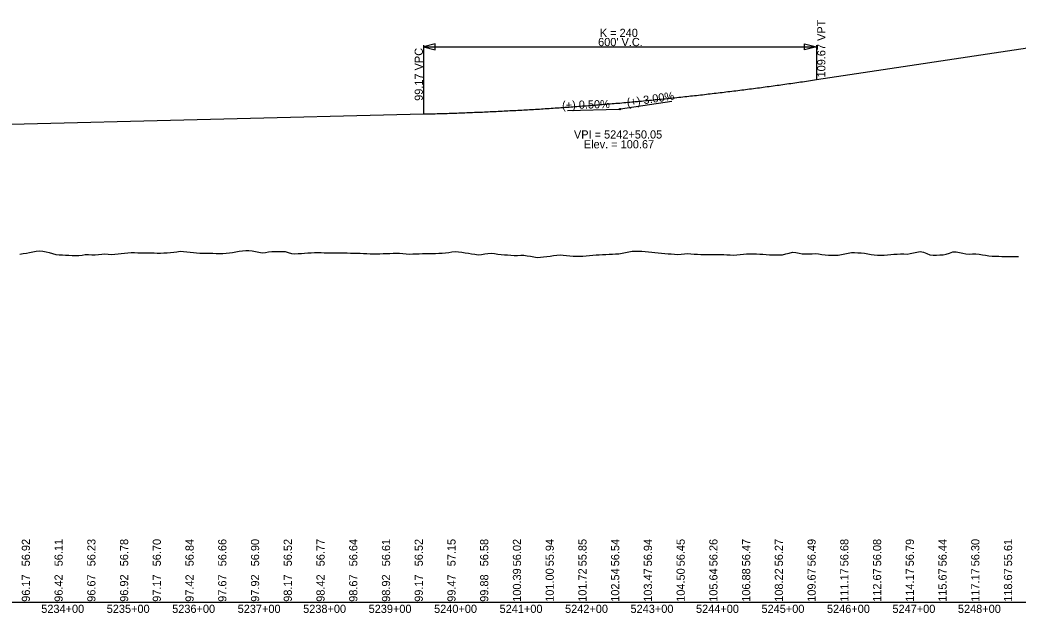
# Model space of a CAD drawing. Extents: x 2147288 to 2220488, y 740833 to 759333.
# Drawn here: x 2155715 to 2157239, y 758067 to 758973 of the extents above; entities that cross this region are included whole.
import ezdxf

# ---------------------------------------------------------------- set-up
doc = ezdxf.new("R2010")
doc.units = 0
for name, color, linetype in [('RD_DDB_GradeTX', 7, 'Continuous'), ('RD_DDB_Profile_EX', 7, 'Continuous'), ('RD_DDB_Profile_Lbl', 7, 'Continuous'), ('RD_DDB_Profile_PR', 7, 'Continuous'), ('RD_DDB_StaTX', 7, 'Continuous'), ('RD_DDB_StripGrade', 7, 'Continuous'), ('RD_DDB_VCLbl', 7, 'Continuous'), ('RD_GPK_Profile_Cell', 7, 'Continuous')]:
    doc.layers.add(name, color=color, linetype=linetype)

msp = doc.modelspace()

# ---------------------------------------------------------------- linework, layer by layer
at = {"layer": 'RD_DDB_GradeTX'}
for p, q in [((2156710.2, 758848.6), (2156632.1, 758836.9)), ((2156551.2, 758834.8), (2156630.1, 758836.7))]:
    msp.add_line(p, q, dxfattribs=at)
msp.add_circle((2156631.1, 758836.8), 1, dxfattribs=at)
at = {"layer": 'RD_DDB_Profile_EX'}
for points in [[(2155714.6, 758615.3), (2155719.6, 758616), (2155724.6, 758616.8), (2155729.6, 758617.7), (2155734.6, 758618.6), (2155739.6, 758619.6), (2155744.6, 758620.1), (2155749.6, 758620), (2155754.6, 758618.9), (2155759.6, 758617.5), (2155764.6, 758616), (2155769.6, 758614.5), (2155774.6, 758614), (2155779.6, 758614.1), (2155784.6, 758613.9), (2155789.6, 758613.6), (2155794.6, 758613.4), (2155799.6, 758613.2), (2155804.6, 758613.4), (2155809.6, 758613.8), (2155814.6, 758614.7), (2155819.6, 758614.7), (2155824.6, 758614), (2155829.6, 758614.4), (2155834.6, 758614.9), (2155839.6, 758615.3), (2155844.6, 758615.7), (2155849.6, 758615.4), (2155854.6, 758614.8), (2155859.6, 758615.3), (2155864.6, 758615.9), (2155869.6, 758616.3), (2155874.6, 758616.8), (2155879.6, 758617.2), (2155884.6, 758617.7), (2155889.6, 758617.5), (2155894.6, 758617.2), (2155899.6, 758617.1), (2155904.6, 758617.2), (2155909.6, 758617.2), (2155914.6, 758617.3), (2155919.6, 758617.2), (2155924.6, 758616.9), (2155929.6, 758616.8), (2155934.6, 758617.1), (2155939.6, 758617.3), (2155944.6, 758617.5), (2155949.6, 758618), (2155954.6, 758618.9), (2155959.6, 758619.7), (2155964.6, 758619.3), (2155969.6, 758618.8), (2155974.6, 758618.3), (2155979.6, 758617.8), (2155984.6, 758617.2), (2155989.6, 758616.7), (2155994.6, 758616.6), (2155999.6, 758616.7), (2156004.6, 758616.7), (2156009.6, 758616.6), (2156014.6, 758616.4), (2156019.6, 758616.3), (2156024.6, 758616.3), (2156029.6, 758616.6), (2156034.6, 758617)], [(2156034.6, 758617), (2156039.6, 758617.9), (2156044.6, 758618.8), (2156049.6, 758619.7), (2156054.6, 758620.5), (2156059.6, 758620.7), (2156064.6, 758620.9), (2156069.6, 758620.4), (2156074.6, 758619.3), (2156079.6, 758618.3), (2156084.6, 758617.2), (2156089.6, 758617.6), (2156094.6, 758618.5), (2156099.6, 758619.3), (2156104.6, 758619.4), (2156109.6, 758619.4), (2156114.6, 758619.5), (2156119.6, 758619.1), (2156124.6, 758617.6), (2156129.6, 758616.1), (2156134.6, 758615.7), (2156139.6, 758616), (2156144.6, 758616.4), (2156149.6, 758616.7), (2156154.6, 758617), (2156159.6, 758617.3), (2156164.6, 758617.6), (2156169.6, 758617.7), (2156174.6, 758617.5), (2156179.6, 758617.3), (2156184.6, 758617.1), (2156189.6, 758617.1), (2156194.6, 758617.2), (2156199.6, 758617.2), (2156204.6, 758617.2), (2156209.6, 758617.1), (2156214.6, 758617), (2156219.6, 758616.9), (2156224.6, 758616.8), (2156229.6, 758616.7), (2156234.6, 758616.5), (2156239.6, 758616.4), (2156244.6, 758616.1), (2156249.6, 758615.9), (2156254.6, 758615.7), (2156259.6, 758615.7), (2156264.6, 758615.9), (2156269.6, 758616.1), (2156274.6, 758616.3), (2156279.6, 758616.4), (2156284.6, 758616.6), (2156289.6, 758616.7), (2156294.6, 758616.6), (2156299.6, 758616.1), (2156304.6, 758615.7), (2156309.6, 758615.4), (2156314.6, 758615.5), (2156319.6, 758615.7), (2156324.6, 758615.9), (2156329.6, 758616), (2156334.6, 758616.1), (2156339.6, 758616.2), (2156344.6, 758616.3), (2156349.6, 758616.4), (2156354.6, 758616.5), (2156359.6, 758616.6), (2156364.6, 758617), (2156369.6, 758617.8), (2156374.6, 758618.6), (2156379.6, 758619.4), (2156384.6, 758618.7), (2156389.6, 758618), (2156394.6, 758617.2), (2156399.6, 758616.5), (2156404.6, 758615.7), (2156409.6, 758615), (2156414.6, 758614.2), (2156419.6, 758614.8), (2156424.6, 758615.5), (2156429.6, 758616.2), (2156434.6, 758616.6), (2156439.6, 758616), (2156444.6, 758615.4), (2156449.6, 758614.8), (2156454.6, 758614.4), (2156459.6, 758614), (2156464.6, 758613.7), (2156469.6, 758613.3), (2156474.6, 758613.4), (2156479.6, 758613.5), (2156484.6, 758613.6), (2156489.6, 758612.8), (2156494.6, 758612), (2156499.6, 758611.1), (2156504.6, 758610.3), (2156509.6, 758610.8), (2156514.6, 758611.2), (2156519.6, 758611.7), (2156524.6, 758612.3), (2156529.6, 758612.9), (2156534.6, 758613.5)], [(2156534.6, 758613.5), (2156539.6, 758614.2), (2156544.6, 758613.6), (2156549.6, 758613), (2156554.6, 758612.4), (2156559.6, 758612.2), (2156564.6, 758612.2), (2156569.6, 758612.1), (2156574.6, 758612.1), (2156579.6, 758612.5), (2156584.6, 758613.1), (2156589.6, 758613.6), (2156594.6, 758614.1), (2156599.6, 758614.3), (2156604.6, 758614.6), (2156609.6, 758614.9), (2156614.6, 758615.1), (2156619.6, 758615.3), (2156624.6, 758615.5), (2156629.6, 758615.8), (2156634.6, 758616.8), (2156639.6, 758617.9), (2156644.6, 758618.9), (2156649.6, 758619.7), (2156654.6, 758619.7), (2156659.6, 758619.6), (2156664.6, 758619.6), (2156669.6, 758619.1), (2156674.6, 758618.7), (2156679.6, 758618.3), (2156684.6, 758617.8), (2156689.6, 758617.3), (2156694.6, 758616.9), (2156699.6, 758616.4), (2156704.6, 758615.9), (2156709.6, 758615.5), (2156714.6, 758615.1), (2156719.6, 758614.7), (2156724.6, 758615.1), (2156729.6, 758615.5), (2156734.6, 758616), (2156739.6, 758615.7), (2156744.6, 758615.3), (2156749.6, 758615), (2156754.6, 758614.7), (2156759.6, 758614.7), (2156764.6, 758614.7), (2156769.6, 758614.7), (2156774.6, 758614.7), (2156779.6, 758614.7), (2156784.6, 758614.7), (2156789.6, 758614.8), (2156794.6, 758614.4), (2156799.6, 758614.1), (2156804.6, 758613.8), (2156809.6, 758614.2), (2156814.6, 758614.7), (2156819.6, 758615.2), (2156824.6, 758615.7), (2156829.6, 758615.8), (2156834.6, 758615.8), (2156839.6, 758615.7), (2156844.6, 758615.4), (2156849.6, 758615.1), (2156854.6, 758614.7), (2156859.6, 758614.3), (2156864.6, 758614.3), (2156869.6, 758614.4), (2156874.6, 758614.4), (2156879.6, 758614.4), (2156884.6, 758615.5), (2156889.6, 758616.9), (2156894.6, 758618.3), (2156899.6, 758617.7), (2156904.6, 758616.6), (2156909.6, 758615.5), (2156914.6, 758615.5), (2156919.6, 758615.7), (2156924.6, 758615.8), (2156929.6, 758616), (2156934.6, 758615.5), (2156939.6, 758614.9), (2156944.6, 758614.3), (2156949.6, 758613.6), (2156954.6, 758613.6), (2156959.6, 758613.7), (2156964.6, 758613.9), (2156969.6, 758614.6), (2156974.6, 758615.6), (2156979.6, 758616.5), (2156984.6, 758617.5), (2156989.6, 758617.6), (2156994.6, 758617.3), (2156999.6, 758617.1), (2157004.6, 758616.5), (2157009.6, 758615.7), (2157014.6, 758614.9), (2157019.6, 758614.2), (2157024.6, 758613.9), (2157029.6, 758613.8), (2157034.6, 758613.8)], [(2157034.6, 758613.8), (2157039.6, 758614.1), (2157044.6, 758614.5), (2157049.6, 758615), (2157054.6, 758615.4), (2157059.6, 758615.5), (2157064.6, 758615.5), (2157069.6, 758615.4), (2157074.6, 758616.1), (2157079.6, 758617.1), (2157084.6, 758618.1), (2157089.6, 758619.1), (2157094.6, 758618.2), (2157099.6, 758616.3), (2157104.6, 758614.3), (2157109.6, 758613.8), (2157114.6, 758613.9), (2157119.6, 758614), (2157124.6, 758614), (2157129.6, 758615.1), (2157134.6, 758616.8), (2157139.6, 758618.5), (2157144.6, 758618.5), (2157149.6, 758617.5), (2157154.6, 758616.6), (2157159.6, 758615.6), (2157164.6, 758615.3), (2157169.6, 758615.5), (2157174.6, 758615.6), (2157179.6, 758615.1), (2157184.6, 758614.3), (2157189.6, 758613.5), (2157194.6, 758612.7), (2157199.6, 758612.3), (2157204.6, 758612.1), (2157209.6, 758612), (2157214.6, 758611.8), (2157219.6, 758611.7), (2157224.6, 758611.6), (2157229.6, 758611.5), (2157234.6, 758611.4), (2157239.6, 758611.4)]]:
    msp.add_lwpolyline(points, dxfattribs=at)
at = {"layer": 'RD_DDB_Profile_PR'}
for p, q in [((2156931.1, 758881.8), (2157281.1, 758934.3)), ((2154731.1, 758789.3), (2156331.1, 758829.3))]:
    msp.add_line(p, q, dxfattribs=at)
msp.add_spline([(2156331.1, 758829.3), (2156343.1, 758829.6), (2156355.1, 758829.9), (2156367.1, 758830.3), (2156379.1, 758830.7), (2156391.1, 758831.1), (2156403.1, 758831.6), (2156415.1, 758832.1), (2156427.1, 758832.6), (2156439.1, 758833.2), (2156451.1, 758833.8), (2156463.1, 758834.4), (2156475.1, 758835), (2156487.1, 758835.7), (2156499.1, 758836.4), (2156511.1, 758837.1), (2156523.1, 758837.9), (2156535.1, 758838.7), (2156547.1, 758839.5), (2156559.1, 758840.4), (2156571.1, 758841.3), (2156583.1, 758842.2), (2156595.1, 758843.1), (2156607.1, 758844.1), (2156619.1, 758845.1), (2156631.1, 758846.1), (2156643.1, 758847.2), (2156655.1, 758848.3), (2156667.1, 758849.4), (2156679.1, 758850.6), (2156691.1, 758851.8), (2156703.1, 758853), (2156715.1, 758854.2), (2156727.1, 758855.5), (2156739.1, 758856.8), (2156751.1, 758858.1), (2156763.1, 758859.5), (2156775.1, 758860.9), (2156787.1, 758862.3), (2156799.1, 758863.8), (2156811.1, 758865.3), (2156823.1, 758866.8), (2156835.1, 758868.3), (2156847.1, 758869.9), (2156859.1, 758871.5), (2156871.1, 758873.1), (2156883.1, 758874.8), (2156895.1, 758876.5), (2156907.1, 758878.2), (2156919.1, 758880), (2156931.1, 758881.8)], degree=3, dxfattribs=at)
at = {"layer": 'RD_DDB_VCLbl'}
for p, q in [((2156331.1, 758934.3), (2156331.1, 758829.3)), ((2156331.1, 758931.8), (2156931.1, 758931.8)), ((2156931.1, 758934.3), (2156931.1, 758881.8))]:
    msp.add_line(p, q, dxfattribs=at)
for points in [[(2156349.1, 758936.3), (2156331.1, 758931.8), (2156349.1, 758927.3)], [(2156913.1, 758936.3), (2156931.1, 758931.8), (2156913.1, 758927.3)]]:
    msp.add_lwpolyline(points, close=True, dxfattribs=at)
at = {"layer": 'RD_GPK_Profile_Cell'}
msp.add_line((2148888.3, 758083.4), (2165888.3, 758083.4), dxfattribs=at)

# ---------------------------------------------------------------- texts
at = {"layer": 'RD_DDB_GradeTX'}
for s, rotation, p in [('(+) 3.00%', 8.5308, (2156642.5, 758840.5)), ('(+) 0.50%', 1.4321, (2156542.9, 758836.6))]:
    msp.add_text(s, height=12.5, rotation=rotation, dxfattribs=at).set_placement(p)
at = {"layer": 'RD_DDB_Profile_Lbl'}
for s, p in [('VPI = 5242+50.05', (2156560.9, 758791.8)), ('Elev. = 100.67', (2156576, 758776.8))]:
    msp.add_text(s, height=12.5, dxfattribs=at).set_placement(p)
at = {"layer": 'RD_DDB_StaTX'}
for s, p in [('5234+00', (2155747.3, 758067.2)), ('5235+00', (2155847.3, 758067.2)), ('5236+00', (2155947.3, 758067.2)), ('5237+00', (2156047.3, 758067.2)), ('5238+00', (2156147.3, 758067.2)), ('5239+00', (2156247.3, 758067.2)), ('5240+00', (2156347.3, 758067.2)), ('5241+00', (2156447.3, 758067.2)), ('5242+00', (2156547.3, 758067.2)), ('5243+00', (2156647.3, 758067.2)), ('5244+00', (2156747.3, 758067.2)), ('5245+00', (2156847.3, 758067.2)), ('5246+00', (2156947.3, 758067.2)), ('5247+00', (2157047.3, 758067.2)), ('5248+00', (2157147.3, 758067.2))]:
    msp.add_text(s, height=12.5, dxfattribs=at).set_placement(p)
at = {"layer": 'RD_DDB_StripGrade'}
for s, p in [('109.67 VPT', (2156944.9, 758885.1)), ('99.17 VPC', (2156330.1, 758849.4)), ('56.92', (2155730.1, 758138.4)), ('56.11', (2155780.1, 758138.4)), ('56.23', (2155830.1, 758138.4)), ('56.78', (2155880.1, 758138.4)), ('56.70', (2155930.1, 758138.4)), ('56.84', (2155980.1, 758138.4)), ('56.66', (2156030.1, 758138.4)), ('56.90', (2156080.1, 758138.4)), ('56.52', (2156130.1, 758138.4)), ('56.77', (2156180.1, 758138.4)), ('56.64', (2156230.1, 758138.4)), ('56.61', (2156280.1, 758138.4)), ('56.52', (2156330.1, 758138.4)), ('57.15', (2156380.1, 758138.4)), ('56.58', (2156430.1, 758138.4)), ('56.02', (2156480.1, 758138.4)), ('55.94', (2156530.1, 758138.4)), ('55.85', (2156580.1, 758138.4)), ('56.54', (2156630.1, 758138.4)), ('56.94', (2156680.1, 758138.4)), ('56.45', (2156730.1, 758138.4)), ('56.26', (2156780.1, 758138.4)), ('56.47', (2156830.1, 758138.4)), ('56.27', (2156880.1, 758138.4)), ('56.49', (2156930.1, 758138.4)), ('56.68', (2156980.1, 758138.4)), ('56.08', (2157030.1, 758138.4)), ('56.79', (2157080.1, 758138.4)), ('56.44', (2157130.1, 758138.4)), ('56.30', (2157180.1, 758138.4)), ('55.61', (2157230.1, 758138.4)), ('96.17', (2155730.1, 758084.2)), ('96.42', (2155780.1, 758084.2)), ('96.67', (2155830.1, 758084.2)), ('96.92', (2155880.1, 758084.2)), ('97.17', (2155930.1, 758084.2)), ('97.42', (2155980.1, 758084.2)), ('97.67', (2156030.1, 758084.2)), ('97.92', (2156080.1, 758084.2)), ('98.17', (2156130.1, 758084.2)), ('98.42', (2156180.1, 758084.2)), ('98.67', (2156230.1, 758084.2)), ('98.92', (2156280.1, 758084.2)), ('99.17', (2156330.1, 758084.2)), ('99.47', (2156380.1, 758084.2)), ('99.88', (2156430.1, 758084.2)), ('100.39', (2156480.1, 758084.2)), ('101.00', (2156530.1, 758084.2)), ('101.72', (2156580.1, 758084.2)), ('102.54', (2156630.1, 758084.2)), ('103.47', (2156680.1, 758084.2)), ('104.50', (2156730.1, 758084.2)), ('105.64', (2156780.1, 758084.2)), ('106.88', (2156830.1, 758084.2)), ('108.22', (2156880.1, 758084.2)), ('109.67', (2156930.1, 758084.2)), ('111.17', (2156980.1, 758084.2)), ('112.67', (2157030.1, 758084.2)), ('114.17', (2157080.1, 758084.2)), ('115.67', (2157130.1, 758084.2)), ('117.17', (2157180.1, 758084.2)), ('118.67', (2157230.1, 758084.2))]:
    msp.add_text(s, height=12.5, rotation=90, dxfattribs=at).set_placement(p)
at = {"layer": 'RD_DDB_VCLbl'}
for s, p in [("600' V.C.", (2156597.8, 758933)), ('K = 240', (2156600.4, 758947))]:
    msp.add_text(s, height=12.5, dxfattribs=at).set_placement(p)

doc.saveas('drawing.dxf')
